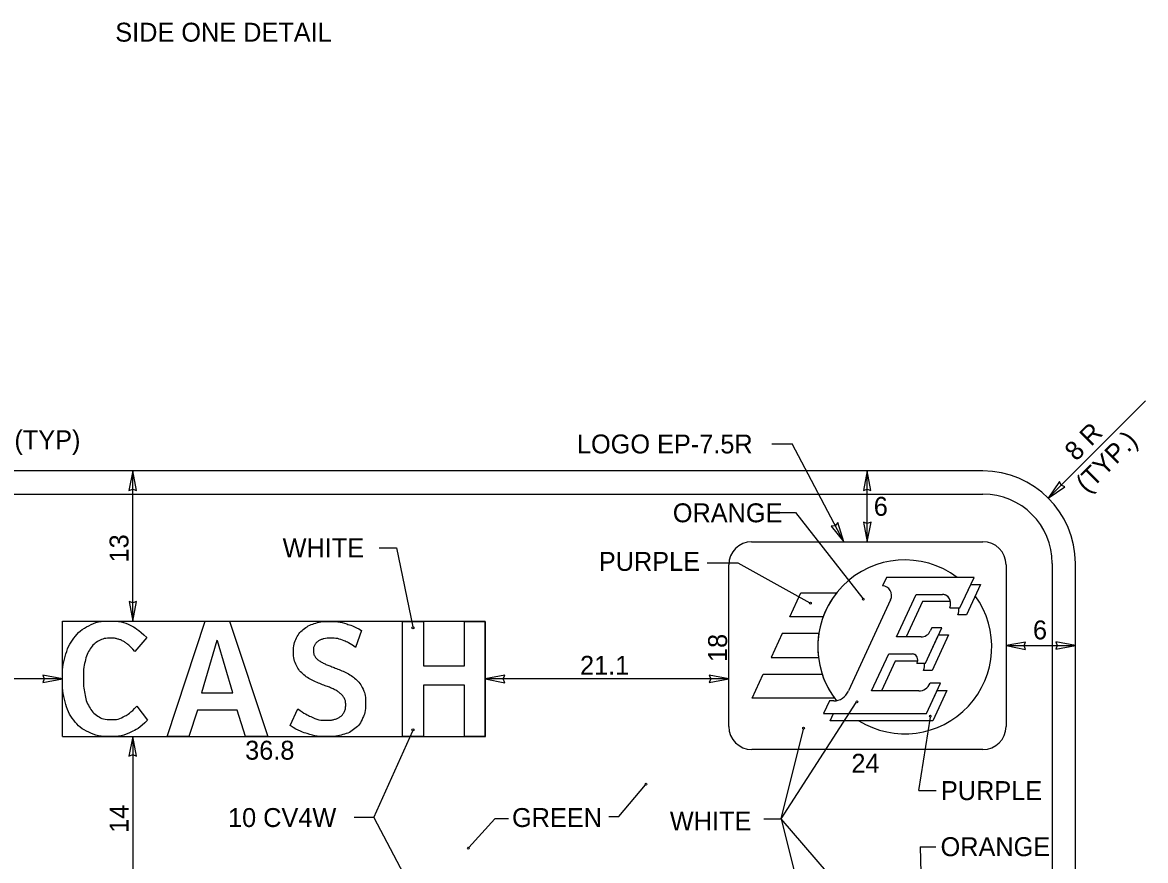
# Model space of a CAD drawing. Extents: x 319706 to 320346, y 1621790 to 1622121.
# Drawn here: x 319772.1 to 319855.2, y 1621873.6 to 1621935.6 of the extents above; entities that cross this region are included whole.
import ezdxf

# ---------------------------------------------------------------- set-up
doc = ezdxf.new("R2010")
doc.units = 0
for name, color, linetype in [('1', 7, 'Continuous'), ('52', 7, 'Continuous'), ('SignPanel', 7, 'Continuous'), ('SOILS_SP83_SHP', 7, 'Continuous')]:
    doc.layers.add(name, color=color, linetype=linetype)

msp = doc.modelspace()

# ---------------------------------------------------------------- linework, layer by layer
at = {"layer": '1'}
for p, q in [((319855.209, 1621907.6), (319848.011, 1621900.402)), ((319827.557, 1621904.403), (319829.054, 1621904.403)), ((319832.865, 1621897.166), (319829.054, 1621904.403)), ((319834.613, 1621897.166), (319834.613, 1621902.405)), ((319828.143, 1621899.321), (319829.291, 1621899.321)), ((319829.291, 1621899.321), (319834.274, 1621892.959)), ((319798.475, 1621896.712), (319799.757, 1621896.712)), ((319799.757, 1621896.712), (319800.986, 1621890.861)), ((319822.761, 1621895.595), (319825.036, 1621895.595)), ((319825.036, 1621895.595), (319830.371, 1621892.637)), ((319844.884, 1621889.471), (319850.014, 1621889.471)), ((319828.244, 1621876.645), (319833.802, 1621885.258)), ((319838.423, 1621878.739), (319839.283, 1621884.175)), ((319798.08, 1621876.744), (319800.986, 1621883.169)), ((319828.244, 1621876.645), (319829.899, 1621883.299)), ((319816.21, 1621876.825), (319818.19, 1621879.16)), ((319838.423, 1621878.739), (319839.706, 1621878.739)), ((319798.08, 1621876.744), (319796.638, 1621876.744)), ((319798.08, 1621876.744), (319801.479, 1621870.318)), ((319807.039, 1621876.644), (319805.127, 1621874.53)), ((319808.063, 1621876.644), (319807.039, 1621876.644)), ((319815.473, 1621876.825), (319816.21, 1621876.825)), ((319826.961, 1621876.645), (319828.244, 1621876.645)), ((319828.244, 1621876.645), (319829.899, 1621869.995)), ((319835.764, 1621867.926), (319828.244, 1621876.645)), ((319838.529, 1621874.588), (319839.677, 1621874.588)), ((319838.529, 1621874.588), (319838.662, 1621869.215))]:
    msp.add_line(p, q, dxfattribs=at)
for centre, major_axis, ratio in [((319830.404, 1621892.611), (0, 0.0707), 0.906668), ((319834.321, 1621892.909), (0, 0.0707), 0.906668), ((319800.986, 1621890.79), (0.0736, 0), 0.960359), ((319833.849, 1621885.307), (0, 0.0707), 0.906668), ((319839.283, 1621884.246), (0, 0.0707), 0.906668), ((319800.986, 1621883.24), (0.0736, 0), 0.960359), ((319829.899, 1621883.369), (0, 0.0707), 0.906668), ((319818.237, 1621879.209), (0, 0.0707), 0.906668), ((319805.08, 1621874.482), (0, 0.0707), 0.906668)]:
    msp.add_ellipse(centre, major_axis=major_axis, ratio=ratio, dxfattribs=at)
at = {"layer": '52'}
for p, q in [((319780.238, 1621902.405), (319779.958, 1621900.955)), ((319780.508, 1621900.955), (319780.238, 1621902.405)), ((319834.613, 1621902.405), (319834.333, 1621900.955)), ((319834.883, 1621900.955), (319834.613, 1621902.405)), ((319848.845, 1621901.618), (319848.011, 1621900.402)), ((319848.958, 1621901.349), (319848.845, 1621901.618)), ((319849.234, 1621901.229), (319848.958, 1621901.349)), ((319779.958, 1621900.955), (319780.238, 1621901.065)), ((319780.238, 1621901.065), (319780.508, 1621900.955)), ((319834.333, 1621900.955), (319834.613, 1621901.065)), ((319834.613, 1621901.065), (319834.883, 1621900.955)), ((319848.011, 1621900.402), (319849.234, 1621901.229)), ((319832.241, 1621898.351), (319831.95, 1621898.323)), ((319831.95, 1621898.323), (319832.865, 1621897.166)), ((319832.437, 1621898.579), (319832.241, 1621898.351)), ((319832.865, 1621897.166), (319832.437, 1621898.579)), ((319834.613, 1621898.506), (319834.343, 1621898.616)), ((319834.343, 1621898.616), (319834.613, 1621897.166)), ((319834.613, 1621897.166), (319834.893, 1621898.616)), ((319834.893, 1621898.616), (319834.613, 1621898.506)), ((319780.238, 1621892.63), (319779.968, 1621892.74)), ((319779.968, 1621892.74), (319780.238, 1621891.29)), ((319780.238, 1621891.29), (319780.518, 1621892.74)), ((319780.518, 1621892.74), (319780.238, 1621892.63)), ((319846.334, 1621889.741), (319844.884, 1621889.471)), ((319846.224, 1621889.471), (319846.334, 1621889.741)), ((319850.014, 1621889.471), (319848.564, 1621889.751)), ((319848.564, 1621889.751), (319848.674, 1621889.471)), ((319844.884, 1621889.471), (319846.334, 1621889.191)), ((319846.334, 1621889.191), (319846.224, 1621889.471)), ((319848.674, 1621889.471), (319848.564, 1621889.201)), ((319848.564, 1621889.201), (319850.014, 1621889.471)), ((319775.034, 1621887.015), (319773.584, 1621887.295)), ((319773.584, 1621887.295), (319773.694, 1621887.015)), ((319807.773, 1621887.274), (319806.323, 1621887.004)), ((319807.663, 1621887.004), (319807.773, 1621887.274)), ((319824.364, 1621887.004), (319822.914, 1621887.284)), ((319822.914, 1621887.284), (319823.024, 1621887.004)), ((319773.694, 1621887.015), (319773.584, 1621886.745)), ((319773.584, 1621886.745), (319775.034, 1621887.015)), ((319806.323, 1621887.004), (319807.773, 1621886.724)), ((319807.773, 1621886.724), (319807.663, 1621887.004)), ((319823.024, 1621887.004), (319822.914, 1621886.734)), ((319822.914, 1621886.734), (319824.364, 1621887.004)), ((319780.238, 1621882.74), (319779.958, 1621881.29)), ((319780.508, 1621881.29), (319780.238, 1621882.74)), ((319779.958, 1621881.29), (319780.238, 1621881.4)), ((319780.238, 1621881.4), (319780.508, 1621881.29))]:
    msp.add_line(p, q, dxfattribs=at)
at = {"layer": 'SignPanel'}
for p, q in [((319843.174, 1621902.405), (319733.733, 1621902.405)), ((319780.238, 1621891.29), (319780.238, 1621902.405)), ((319733.733, 1621900.695), (319843.174, 1621900.695)), ((319826.054, 1621897.166), (319843.173, 1621897.166)), ((319848.304, 1621895.565), (319848.304, 1621857.945)), ((319850.014, 1621857.945), (319850.014, 1621895.565)), ((319824.364, 1621883.486), (319824.364, 1621895.457)), ((319844.884, 1621895.457), (319844.884, 1621883.486)), ((319836.038, 1621894.52), (319835.75, 1621893.892)), ((319842.512, 1621894.52), (319836.038, 1621894.52)), ((319841.474, 1621892.277), (319842.512, 1621894.52)), ((319841.474, 1621892.277), (319842.268, 1621893.991)), ((319842.985, 1621893.991), (319841.95, 1621891.746)), ((319842.268, 1621893.991), (319842.985, 1621893.991)), ((319828.879, 1621891.604), (319829.694, 1621893.372)), ((319829.694, 1621893.372), (319832.335, 1621893.372)), ((319836.779, 1621890.113), (319838.233, 1621893.262)), ((319836.779, 1621890.113), (319838.233, 1621893.262)), ((319838.233, 1621893.262), (319840.174, 1621893.262)), ((319838.233, 1621893.262), (319840.174, 1621893.262)), ((319836.34, 1621892.862), (319833.222, 1621886.114)), ((319838.708, 1621892.732), (319837.497, 1621890.113)), ((319840.769, 1621892.732), (319838.708, 1621892.732)), ((319840.714, 1621892.277), (319841.474, 1621892.277)), ((319841.361, 1621892.277), (319841.474, 1621892.277)), ((319831.344, 1621891.604), (319828.879, 1621891.604)), ((319831.344, 1621891.604), (319831.344, 1621891.604)), ((319841.95, 1621891.746), (319841.324, 1621891.746)), ((319838.934, 1621888.174), (319840.142, 1621890.793)), ((319839.379, 1621890.793), (319839.279, 1621890.57)), ((319840.142, 1621890.793), (319839.379, 1621890.793)), ((319828.305, 1621890.365), (319827.489, 1621888.598)), ((319831.024, 1621890.365), (319828.305, 1621890.365)), ((319838.601, 1621890.113), (319836.779, 1621890.113)), ((319837.497, 1621890.113), (319836.779, 1621890.113)), ((319838.934, 1621888.174), (319839.896, 1621890.261)), ((319840.618, 1621890.261), (319839.407, 1621887.642)), ((319839.898, 1621890.261), (319840.618, 1621890.261)), ((319834.935, 1621886.122), (319836.197, 1621888.854)), ((319834.935, 1621886.122), (319836.197, 1621888.854)), ((319836.197, 1621888.854), (319837.952, 1621888.854)), ((319836.197, 1621888.854), (319837.952, 1621888.854)), ((319827.489, 1621888.598), (319830.994, 1621888.598)), ((319836.671, 1621888.322), (319835.654, 1621886.122)), ((319838.346, 1621888.322), (319836.671, 1621888.322)), ((319838.288, 1621888.174), (319838.934, 1621888.174)), ((319838.819, 1621888.174), (319838.934, 1621888.174)), ((319826.101, 1621885.591), (319826.917, 1621887.359)), ((319826.917, 1621887.359), (319831.274, 1621887.359)), ((319839.407, 1621887.642), (319838.782, 1621887.642)), ((319775.034, 1621887.015), (319756.605, 1621887.015)), ((319824.364, 1621887.004), (319806.323, 1621887.004)), ((319838.999, 1621884.445), (319840.036, 1621886.688)), ((319840.036, 1621886.688), (319839.273, 1621886.688)), ((319832.181, 1621885.591), (319826.101, 1621885.591)), ((319838.43, 1621886.122), (319834.935, 1621886.122)), ((319835.654, 1621886.122), (319834.935, 1621886.122)), ((319838.429, 1621886.124), (319838.43, 1621886.122)), ((319838.999, 1621884.445), (319839.791, 1621886.158)), ((319840.51, 1621886.158), (319839.473, 1621883.913)), ((319839.791, 1621886.158), (319840.51, 1621886.158)), ((319831.818, 1621885.378), (319831.384, 1621884.445)), ((319832.137, 1621885.378), (319831.818, 1621885.378)), ((319831.384, 1621884.445), (319838.999, 1621884.445)), ((319831.86, 1621883.913), (319832.104, 1621884.445)), ((319839.473, 1621883.913), (319831.86, 1621883.913)), ((319832.104, 1621884.445), (319838.999, 1621884.445)), ((319780.238, 1621882.74), (319780.238, 1621870.748)), ((319843.173, 1621881.777), (319826.075, 1621881.777))]:
    msp.add_line(p, q, dxfattribs=at)
for points in [[(319788.599, 1621882.74), (319787.977, 1621884.689), (319785.027, 1621884.689), (319784.404, 1621882.74), (319782.801, 1621882.74), (319785.598, 1621891.29), (319787.397, 1621891.29), (319790.253, 1621882.74), (319788.599, 1621882.74)], [(319797.173, 1621890.597), (319796.733, 1621889.344)], [(319804.792, 1621882.74), (319804.792, 1621886.535), (319801.752, 1621886.535), (319801.752, 1621882.74), (319800.22, 1621882.74), (319800.22, 1621891.268), (319801.752, 1621891.268), (319801.752, 1621887.971), (319804.792, 1621887.971), (319804.792, 1621891.268), (319806.323, 1621891.268), (319806.323, 1621882.74), (319804.792, 1621882.74)], [(319781.273, 1621890.074), (319780.388, 1621889.047)], [(319786.519, 1621889.839), (319786.476, 1621889.841), (319785.333, 1621885.971), (319787.661, 1621885.971), (319786.519, 1621889.839)], [(319780.542, 1621884.984), (319781.337, 1621883.949)], [(319791.887, 1621883.553), (319792.452, 1621884.797)]]:
    msp.add_lwpolyline(points, dxfattribs=at)
for centre, radius, start, end in [((319843.174, 1621895.565), 6.84, 0, 90), ((319843.174, 1621895.565), 5.13, 0, 90), ((319826.074, 1621895.456), 1.71, 90.65967, 180), ((319843.173, 1621895.456), 1.71, 0, 90), ((319837.386, 1621889.381), 6.438, 52.95752, 218.23265), ((319837.386, 1621889.381), 6.438, 141.69261, 159.80147), ((319837.386, 1621889.381), 6.438, 238.13256, 35.91001), ((319837.386, 1621889.381), 6.438, 171.20754, 186.98296), ((319837.386, 1621889.381), 6.438, 198.3, 216.05763), ((319826.074, 1621883.487), 1.71, 180, 270), ((319843.173, 1621883.487), 1.71, 270, 360)]:
    msp.add_arc(centre, radius, start, end, dxfattribs=at)
for centre, major_axis, start_param, end_param in [((319835.768, 1621893.184), (0, 0.707), 4.241328, 6.314398), ((319840.174, 1621892.59), (0, 0.672), 4.227342, 6.283185), ((319840.174, 1621892.59), (0, 0.672), 4.924621, 6.283185), ((319840.784, 1621892.06), (0, 0.672), 4.227342, 5.041732), ((319838.6, 1621890.952), (0, 0.84), 3.141593, 4.241405), ((319837.951, 1621888.411), (0, 0.442), 4.144801, 6.283185), ((319837.951, 1621888.411), (0, 0.442), 4.51088, 6.283185), ((319838.243, 1621887.956), (0, 0.672), 4.227342, 5.041732), ((319838.429, 1621887.173), (0, 1.05), 3.141593, 4.232591), ((319832.136, 1621886.723), (0, 1.344), 3.141593, 4.241135)]:
    msp.add_ellipse(centre, major_axis=major_axis, ratio=0.906668, start_param=start_param, end_param=end_param, dxfattribs=at)
for points in [[(319781.337, 1621883.949), (319780.766, 1621883.369), (319780.09, 1621883.054), (319779.415, 1621882.739), (319778.587, 1621882.739), (319777.651, 1621882.739), (319776.98, 1621883.062), (319776.309, 1621883.385), (319775.875, 1621883.96), (319775.44, 1621884.536), (319775.237, 1621885.322), (319775.034, 1621886.108), (319775.034, 1621887.035), (319775.034, 1621887.896), (319775.245, 1621888.666), (319775.456, 1621889.436), (319775.89, 1621890.02), (319776.325, 1621890.603), (319776.995, 1621890.947), (319777.665, 1621891.29), (319778.592, 1621891.29), (319779.403, 1621891.29), (319780.036, 1621890.988), (319780.669, 1621890.686), (319781.273, 1621890.074)], [(319792.452, 1621884.797), (319792.933, 1621884.442), (319793.468, 1621884.193), (319794.004, 1621883.945), (319794.618, 1621883.945), (319794.883, 1621883.945), (319795.132, 1621884.003), (319795.381, 1621884.061), (319795.576, 1621884.194), (319795.771, 1621884.326), (319795.887, 1621884.546), (319796.003, 1621884.766), (319796.003, 1621885.097), (319796.003, 1621885.387), (319795.883, 1621885.603), (319795.762, 1621885.819), (319795.555, 1621885.98), (319795.348, 1621886.142), (319795.078, 1621886.266), (319794.808, 1621886.391), (319794.501, 1621886.498), (319794.095, 1621886.656), (319793.676, 1621886.843), (319793.257, 1621887.029), (319792.916, 1621887.311), (319792.576, 1621887.594), (319792.361, 1621888.004), (319792.145, 1621888.415), (319792.145, 1621889.021), (319792.145, 1621889.618), (319792.365, 1621890.041), (319792.585, 1621890.464), (319792.954, 1621890.738), (319793.323, 1621891.012), (319793.796, 1621891.141), (319794.269, 1621891.269), (319794.775, 1621891.269), (319795.447, 1621891.269), (319796.032, 1621891.091), (319796.617, 1621890.913), (319797.173, 1621890.597)], [(319780.388, 1621889.047), (319780.182, 1621889.287), (319779.983, 1621889.469), (319779.785, 1621889.652), (319779.574, 1621889.776), (319779.363, 1621889.9), (319779.131, 1621889.962), (319778.9, 1621890.024), (319778.627, 1621890.024), (319778.114, 1621890.024), (319777.734, 1621889.821), (319777.354, 1621889.618), (319777.097, 1621889.234), (319776.841, 1621888.849), (319776.713, 1621888.294), (319776.585, 1621887.74), (319776.585, 1621887.036), (319776.585, 1621886.465), (319776.684, 1621885.923), (319776.784, 1621885.381), (319777.019, 1621884.95), (319777.255, 1621884.52), (319777.649, 1621884.259), (319778.042, 1621883.998), (319778.63, 1621883.998), (319779.193, 1621883.998), (319779.636, 1621884.243), (319780.079, 1621884.487), (319780.542, 1621884.984)], [(319796.733, 1621889.344), (319796.302, 1621889.658), (319795.866, 1621889.84), (319795.431, 1621890.021), (319794.883, 1621890.021), (319794.626, 1621890.021), (319794.398, 1621889.976), (319794.17, 1621889.93), (319793.996, 1621889.818), (319793.821, 1621889.706), (319793.718, 1621889.524), (319793.614, 1621889.342), (319793.614, 1621889.077), (319793.614, 1621888.828), (319793.747, 1621888.646), (319793.879, 1621888.464), (319794.103, 1621888.319), (319794.327, 1621888.174), (319794.618, 1621888.058), (319794.908, 1621887.942), (319795.223, 1621887.818), (319795.621, 1621887.668), (319796.024, 1621887.473), (319796.426, 1621887.278), (319796.749, 1621886.988), (319797.073, 1621886.698), (319797.276, 1621886.274), (319797.479, 1621885.851), (319797.479, 1621885.246)], [(319797.479, 1621885.246), (319797.479, 1621884.582), (319797.268, 1621884.109), (319797.056, 1621883.636), (319796.683, 1621883.329), (319796.31, 1621883.022), (319795.799, 1621882.881), (319795.289, 1621882.74), (319794.692, 1621882.74), (319793.879, 1621882.74), (319793.207, 1621882.939), (319792.535, 1621883.138), (319791.887, 1621883.553)]]:
    msp.add_open_spline(points, degree=3, dxfattribs=at)
at = {"layer": 'SOILS_SP83_SHP'}
for p, q in [((319775.034, 1621891.29), (319806.323, 1621891.29)), ((319775.034, 1621882.74), (319775.034, 1621891.29)), ((319806.323, 1621882.707), (319806.323, 1621891.194)), ((319775.034, 1621882.74), (319806.323, 1621882.74))]:
    msp.add_line(p, q, dxfattribs=at)

# ---------------------------------------------------------------- texts
at = {"layer": '1'}
for s, p in [('SIDE ONE DETAIL', (319778.949, 1621934.188)), ('2 WHITE (TYP)', (319763.371, 1621904.012)), ('LOGO EP-7.5R', (319813.123, 1621903.703)), ('6', (319835.091, 1621899.085)), ('ORANGE', (319820.218, 1621898.605)), ('WHITE', (319791.339, 1621896.012)), ('PURPLE', (319814.74, 1621895.007)), ('6', (319846.877, 1621889.936)), ('21.1', (319813.35, 1621887.315)), ('36.8', (319788.563, 1621881.03)), ('24', (319833.436, 1621880.064)), ('PURPLE', (319840.066, 1621878.039)), ('10 CV4W', (319787.296, 1621876.044)), ('GREEN', (319808.318, 1621876.044)), ('WHITE', (319819.999, 1621875.789)), ('ORANGE', (319840.037, 1621873.888))]:
    msp.add_text(s, height=1.4, dxfattribs=at).set_placement(p)
for s, rotation, p in [('8 R', 45, (319850.072, 1621903.068)), ('(TYP.)', 45, (319850.892, 1621900.698)), ('13', 90, (319779.928, 1621895.631)), ('18', 90, (319824.234, 1621888.26)), ('14', 90, (319779.928, 1621875.614))]:
    msp.add_text(s, height=1.4, rotation=rotation, dxfattribs=at).set_placement(p)

doc.saveas('drawing.dxf')
